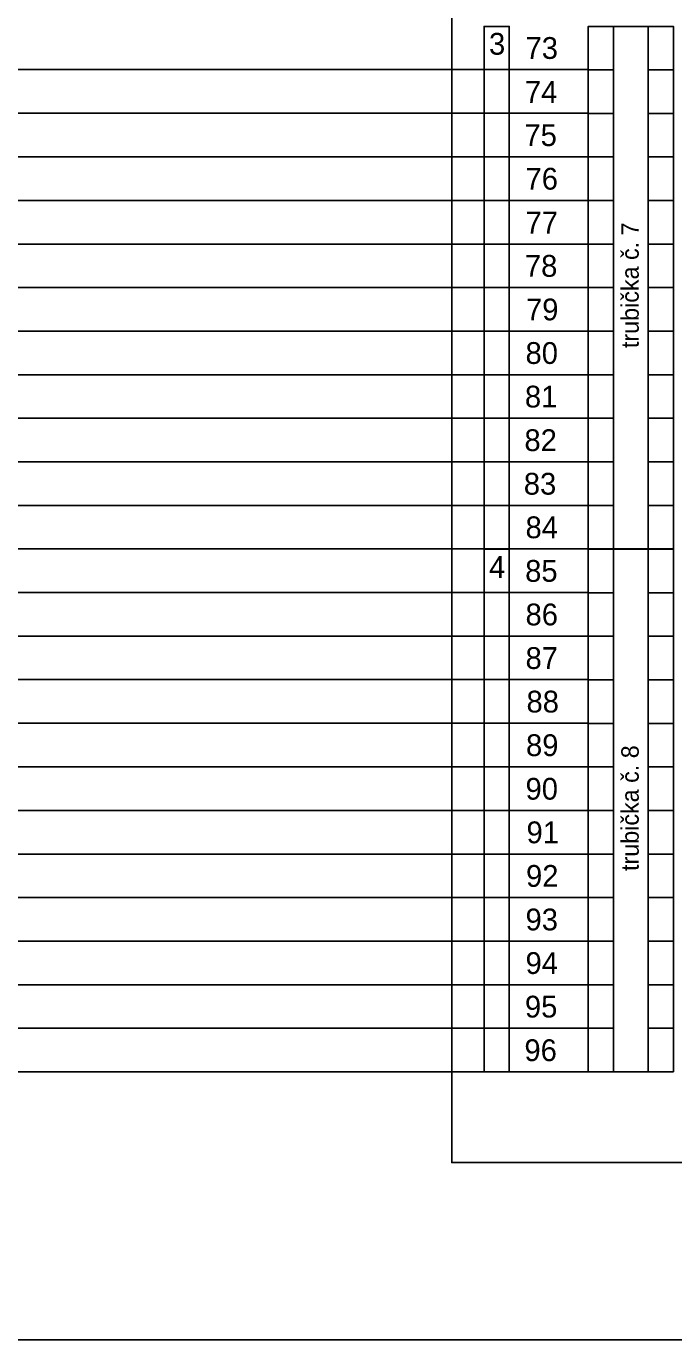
# Model space of a CAD drawing. Extents: x 1901 to 2519, y -3585 to -3154.
# Drawn here: x 1980.5 to 2032.8, y -3585 to -3478.9 of the extents above; entities that cross this region are included whole.
import ezdxf

# ---------------------------------------------------------------- set-up
doc = ezdxf.new("R2010")
doc.units = 0
doc.layers.add('rozvláknění', color=7, linetype='Continuous')
doc.layers.add('Vrstva 4', color=7, linetype='Continuous')

msp = doc.modelspace()

# ---------------------------------------------------------------- linework, layer by layer
at = {"layer": 'rozvláknění'}
for p, q in [((1933.19, -3482.36), (2025.9, -3482.36)), ((1933.19, -3485.88), (2025.9, -3485.88)), ((1933.19, -3489.4), (2025.9, -3489.4)), ((1933.19, -3492.94), (2025.9, -3492.94)), ((1933.19, -3496.46), (2025.9, -3496.46)), ((1933.19, -3499.97), (2025.9, -3499.98)), ((1933.19, -3503.49), (2025.9, -3503.49)), ((1933.19, -3507.01), (2025.9, -3507.01)), ((1933.19, -3510.53), (2025.9, -3510.53)), ((1933.19, -3514.05), (2025.9, -3514.05)), ((1933.19, -3517.56), (2025.9, -3517.57)), ((1933.19, -3521.08), (2025.9, -3521.08)), ((1933.19, -3524.6), (2025.9, -3524.6)), ((1933.19, -3528.12), (2025.9, -3528.12)), ((1933.19, -3531.64), (2025.9, -3531.64)), ((1933.19, -3535.16), (2025.9, -3535.16)), ((1933.19, -3538.67), (2025.9, -3538.68)), ((1933.19, -3542.21), (2025.9, -3542.22)), ((1933.19, -3545.73), (2025.9, -3545.73)), ((1933.19, -3549.25), (2025.9, -3549.25)), ((1933.19, -3552.77), (2025.9, -3552.77)), ((1933.19, -3556.29), (2025.9, -3556.29)), ((1933.19, -3559.8), (2025.9, -3559.81)), ((1933.19, -3563.32), (2025.9, -3563.32))]:
    msp.add_line(p, q, dxfattribs=at)
for points in [[(2014.87, -3178.54), (2059.52, -3178.54), (2059.52, -3570.66), (2014.87, -3570.66)], [(2019.52, -3521.08), (2017.48, -3521.08), (2017.48, -3478.87), (2019.52, -3478.87)], [(2025.9, -3478.87), (2027.94, -3478.87), (2027.94, -3482.38), (2025.9, -3482.38)], [(2025.9, -3478.87), (2027.94, -3478.87), (2027.94, -3482.38), (2025.9, -3482.38)], [(2027.94, -3478.87), (2030.73, -3478.87), (2030.73, -3521.08), (2027.94, -3521.08)], [(2030.73, -3478.87), (2032.77, -3478.87), (2032.77, -3482.38), (2030.73, -3482.38)], [(2030.73, -3478.87), (2032.77, -3478.87), (2032.77, -3482.38), (2030.73, -3482.38)], [(2025.9, -3482.38), (2027.94, -3482.38), (2027.94, -3485.9), (2025.9, -3485.9)], [(2025.9, -3482.38), (2027.94, -3482.38), (2027.94, -3485.9), (2025.9, -3485.9)], [(2030.73, -3482.38), (2032.77, -3482.38), (2032.77, -3485.9), (2030.73, -3485.9)], [(2030.73, -3482.38), (2032.77, -3482.38), (2032.77, -3485.9), (2030.73, -3485.9)], [(2025.9, -3485.9), (2027.94, -3485.9), (2027.94, -3489.42), (2025.9, -3489.42)], [(2025.9, -3485.9), (2027.94, -3485.9), (2027.94, -3489.42), (2025.9, -3489.42)], [(2030.73, -3485.9), (2032.77, -3485.9), (2032.77, -3489.42), (2030.73, -3489.42)], [(2030.73, -3485.9), (2032.77, -3485.9), (2032.77, -3489.42), (2030.73, -3489.42)], [(2025.9, -3489.42), (2027.94, -3489.42), (2027.94, -3492.94), (2025.9, -3492.94)], [(2025.9, -3489.42), (2027.94, -3489.42), (2027.94, -3492.94), (2025.9, -3492.94)], [(2030.73, -3489.42), (2032.77, -3489.42), (2032.77, -3492.94), (2030.73, -3492.94)], [(2030.73, -3489.42), (2032.77, -3489.42), (2032.77, -3492.94), (2030.73, -3492.94)], [(2025.9, -3492.94), (2027.94, -3492.94), (2027.94, -3496.46), (2025.9, -3496.46)], [(2025.9, -3492.94), (2027.94, -3492.94), (2027.94, -3496.46), (2025.9, -3496.46)], [(2030.73, -3492.94), (2032.77, -3492.94), (2032.77, -3496.46), (2030.73, -3496.46)], [(2030.73, -3492.94), (2032.77, -3492.94), (2032.77, -3496.46), (2030.73, -3496.46)], [(2025.9, -3496.46), (2027.94, -3496.46), (2027.94, -3499.98), (2025.9, -3499.98)], [(2025.9, -3496.46), (2027.94, -3496.46), (2027.94, -3499.98), (2025.9, -3499.98)], [(2030.73, -3496.46), (2032.77, -3496.46), (2032.77, -3499.98), (2030.73, -3499.98)], [(2030.73, -3496.46), (2032.77, -3496.46), (2032.77, -3499.98), (2030.73, -3499.98)], [(2025.9, -3499.98), (2027.94, -3499.98), (2027.94, -3503.49), (2025.9, -3503.49)], [(2025.9, -3499.98), (2027.94, -3499.98), (2027.94, -3503.49), (2025.9, -3503.49)], [(2030.73, -3499.98), (2032.77, -3499.98), (2032.77, -3503.49), (2030.73, -3503.49)], [(2030.73, -3499.98), (2032.77, -3499.98), (2032.77, -3503.49), (2030.73, -3503.49)], [(2025.9, -3503.49), (2027.94, -3503.49), (2027.94, -3507.01), (2025.9, -3507.01)], [(2025.9, -3503.49), (2027.94, -3503.49), (2027.94, -3507.01), (2025.9, -3507.01)], [(2030.73, -3503.49), (2032.77, -3503.49), (2032.77, -3507.01), (2030.73, -3507.01)], [(2030.73, -3503.49), (2032.77, -3503.49), (2032.77, -3507.01), (2030.73, -3507.01)], [(2025.9, -3507.01), (2027.94, -3507.01), (2027.94, -3510.53), (2025.9, -3510.53)], [(2025.9, -3507.01), (2027.94, -3507.01), (2027.94, -3510.53), (2025.9, -3510.53)], [(2030.73, -3507.01), (2032.77, -3507.01), (2032.77, -3510.53), (2030.73, -3510.53)], [(2030.73, -3507.01), (2032.77, -3507.01), (2032.77, -3510.53), (2030.73, -3510.53)], [(2025.9, -3510.53), (2027.94, -3510.53), (2027.94, -3514.05), (2025.9, -3514.05)], [(2025.9, -3510.53), (2027.94, -3510.53), (2027.94, -3514.05), (2025.9, -3514.05)], [(2030.73, -3510.53), (2032.77, -3510.53), (2032.77, -3514.05), (2030.73, -3514.05)], [(2030.73, -3510.53), (2032.77, -3510.53), (2032.77, -3514.05), (2030.73, -3514.05)], [(2025.9, -3514.05), (2027.94, -3514.05), (2027.94, -3517.57), (2025.9, -3517.57)], [(2025.9, -3514.05), (2027.94, -3514.05), (2027.94, -3517.57), (2025.9, -3517.57)], [(2030.73, -3514.05), (2032.77, -3514.05), (2032.77, -3517.57), (2030.73, -3517.57)], [(2030.73, -3514.05), (2032.77, -3514.05), (2032.77, -3517.57), (2030.73, -3517.57)], [(2025.9, -3517.57), (2027.94, -3517.57), (2027.94, -3521.08), (2025.9, -3521.08)], [(2025.9, -3517.57), (2027.94, -3517.57), (2027.94, -3521.08), (2025.9, -3521.08)], [(2030.73, -3517.57), (2032.77, -3517.57), (2032.77, -3521.08), (2030.73, -3521.08)], [(2030.73, -3517.57), (2032.77, -3517.57), (2032.77, -3521.08), (2030.73, -3521.08)], [(2019.52, -3563.32), (2017.48, -3563.32), (2017.48, -3521.11), (2019.52, -3521.11)], [(2025.9, -3521.11), (2027.94, -3521.11), (2027.94, -3524.62), (2025.9, -3524.62)], [(2025.9, -3521.11), (2027.94, -3521.11), (2027.94, -3524.62), (2025.9, -3524.62)], [(2027.94, -3521.11), (2030.73, -3521.11), (2030.73, -3563.32), (2027.94, -3563.32)], [(2030.73, -3521.11), (2032.77, -3521.11), (2032.77, -3524.62), (2030.73, -3524.62)], [(2030.73, -3521.11), (2032.77, -3521.11), (2032.77, -3524.62), (2030.73, -3524.62)], [(2025.9, -3524.62), (2027.94, -3524.62), (2027.94, -3528.14), (2025.9, -3528.14)], [(2025.9, -3524.62), (2027.94, -3524.62), (2027.94, -3528.14), (2025.9, -3528.14)], [(2030.73, -3524.62), (2032.77, -3524.62), (2032.77, -3528.14), (2030.73, -3528.14)], [(2030.73, -3524.62), (2032.77, -3524.62), (2032.77, -3528.14), (2030.73, -3528.14)], [(2025.9, -3528.14), (2027.94, -3528.14), (2027.94, -3531.66), (2025.9, -3531.66)], [(2025.9, -3528.14), (2027.94, -3528.14), (2027.94, -3531.66), (2025.9, -3531.66)], [(2030.73, -3528.14), (2032.77, -3528.14), (2032.77, -3531.66), (2030.73, -3531.66)], [(2030.73, -3528.14), (2032.77, -3528.14), (2032.77, -3531.66), (2030.73, -3531.66)], [(2025.9, -3531.66), (2027.94, -3531.66), (2027.94, -3535.18), (2025.9, -3535.18)], [(2025.9, -3531.66), (2027.94, -3531.66), (2027.94, -3535.18), (2025.9, -3535.18)], [(2030.73, -3531.66), (2032.77, -3531.66), (2032.77, -3535.18), (2030.73, -3535.18)], [(2030.73, -3531.66), (2032.77, -3531.66), (2032.77, -3535.18), (2030.73, -3535.18)], [(2025.9, -3535.18), (2027.94, -3535.18), (2027.94, -3538.7), (2025.9, -3538.7)], [(2025.9, -3535.18), (2027.94, -3535.18), (2027.94, -3538.7), (2025.9, -3538.7)], [(2030.73, -3535.18), (2032.77, -3535.18), (2032.77, -3538.7), (2030.73, -3538.7)], [(2030.73, -3535.18), (2032.77, -3535.18), (2032.77, -3538.7), (2030.73, -3538.7)], [(2025.9, -3538.7), (2027.94, -3538.7), (2027.94, -3542.22), (2025.9, -3542.22)], [(2025.9, -3538.7), (2027.94, -3538.7), (2027.94, -3542.22), (2025.9, -3542.22)], [(2030.73, -3538.7), (2032.77, -3538.7), (2032.77, -3542.22), (2030.73, -3542.22)], [(2030.73, -3538.7), (2032.77, -3538.7), (2032.77, -3542.22), (2030.73, -3542.22)], [(2025.9, -3542.22), (2027.94, -3542.22), (2027.94, -3545.73), (2025.9, -3545.73)], [(2025.9, -3542.22), (2027.94, -3542.22), (2027.94, -3545.73), (2025.9, -3545.73)], [(2030.73, -3542.22), (2032.77, -3542.22), (2032.77, -3545.73), (2030.73, -3545.73)], [(2030.73, -3542.22), (2032.77, -3542.22), (2032.77, -3545.73), (2030.73, -3545.73)], [(2025.9, -3545.73), (2027.94, -3545.73), (2027.94, -3549.25), (2025.9, -3549.25)], [(2025.9, -3545.73), (2027.94, -3545.73), (2027.94, -3549.25), (2025.9, -3549.25)], [(2030.73, -3545.73), (2032.77, -3545.73), (2032.77, -3549.25), (2030.73, -3549.25)], [(2030.73, -3545.73), (2032.77, -3545.73), (2032.77, -3549.25), (2030.73, -3549.25)], [(2025.9, -3549.25), (2027.94, -3549.25), (2027.94, -3552.77), (2025.9, -3552.77)], [(2025.9, -3549.25), (2027.94, -3549.25), (2027.94, -3552.77), (2025.9, -3552.77)], [(2030.73, -3549.25), (2032.77, -3549.25), (2032.77, -3552.77), (2030.73, -3552.77)], [(2030.73, -3549.25), (2032.77, -3549.25), (2032.77, -3552.77), (2030.73, -3552.77)], [(2025.9, -3552.77), (2027.94, -3552.77), (2027.94, -3556.29), (2025.9, -3556.29)], [(2025.9, -3552.77), (2027.94, -3552.77), (2027.94, -3556.29), (2025.9, -3556.29)], [(2030.73, -3552.77), (2032.77, -3552.77), (2032.77, -3556.29), (2030.73, -3556.29)], [(2030.73, -3552.77), (2032.77, -3552.77), (2032.77, -3556.29), (2030.73, -3556.29)], [(2025.9, -3556.29), (2027.94, -3556.29), (2027.94, -3559.81), (2025.9, -3559.81)], [(2025.9, -3556.29), (2027.94, -3556.29), (2027.94, -3559.81), (2025.9, -3559.81)], [(2030.73, -3556.29), (2032.77, -3556.29), (2032.77, -3559.81), (2030.73, -3559.81)], [(2030.73, -3556.29), (2032.77, -3556.29), (2032.77, -3559.81), (2030.73, -3559.81)], [(2025.9, -3559.81), (2027.94, -3559.81), (2027.94, -3563.32), (2025.9, -3563.32)], [(2025.9, -3559.81), (2027.94, -3559.81), (2027.94, -3563.32), (2025.9, -3563.32)], [(2030.73, -3559.81), (2032.77, -3559.81), (2032.77, -3563.32), (2030.73, -3563.32)], [(2030.73, -3559.81), (2032.77, -3559.81), (2032.77, -3563.32), (2030.73, -3563.32)]]:
    msp.add_lwpolyline(points, close=True, dxfattribs=at)
for points in [[(2019.52, -3478.87), (2017.48, -3478.87), (2017.48, -3521.08), (2019.52, -3521.08), (2019.52, -3478.87)], [(2025.9, -3482.38), (2027.94, -3482.38), (2027.94, -3478.87), (2025.9, -3478.87), (2025.9, -3482.38)], [(2030.73, -3482.38), (2032.77, -3482.38), (2032.77, -3478.87), (2030.73, -3478.87), (2030.73, -3482.38)], [(2025.9, -3485.9), (2027.94, -3485.9), (2027.94, -3482.38), (2025.9, -3482.38), (2025.9, -3485.9)], [(2030.73, -3485.9), (2032.77, -3485.9), (2032.77, -3482.38), (2030.73, -3482.38), (2030.73, -3485.9)], [(2025.9, -3489.42), (2027.94, -3489.42), (2027.94, -3485.9), (2025.9, -3485.9), (2025.9, -3489.42)], [(2030.73, -3489.42), (2032.77, -3489.42), (2032.77, -3485.9), (2030.73, -3485.9), (2030.73, -3489.42)], [(2025.9, -3492.94), (2027.94, -3492.94), (2027.94, -3489.42), (2025.9, -3489.42), (2025.9, -3492.94)], [(2030.73, -3492.94), (2032.77, -3492.94), (2032.77, -3489.42), (2030.73, -3489.42), (2030.73, -3492.94)], [(2025.9, -3496.46), (2027.94, -3496.46), (2027.94, -3492.94), (2025.9, -3492.94), (2025.9, -3496.46)], [(2030.73, -3496.46), (2032.77, -3496.46), (2032.77, -3492.94), (2030.73, -3492.94), (2030.73, -3496.46)], [(2025.9, -3499.98), (2027.94, -3499.98), (2027.94, -3496.46), (2025.9, -3496.46), (2025.9, -3499.98)], [(2030.73, -3499.98), (2032.77, -3499.98), (2032.77, -3496.46), (2030.73, -3496.46), (2030.73, -3499.98)], [(2025.9, -3503.49), (2027.94, -3503.49), (2027.94, -3499.98), (2025.9, -3499.98), (2025.9, -3503.49)], [(2030.73, -3503.49), (2032.77, -3503.49), (2032.77, -3499.98), (2030.73, -3499.98), (2030.73, -3503.49)], [(2025.9, -3507.01), (2027.94, -3507.01), (2027.94, -3503.49), (2025.9, -3503.49), (2025.9, -3507.01)], [(2030.73, -3507.01), (2032.77, -3507.01), (2032.77, -3503.49), (2030.73, -3503.49), (2030.73, -3507.01)], [(2025.9, -3510.53), (2027.94, -3510.53), (2027.94, -3507.01), (2025.9, -3507.01), (2025.9, -3510.53)], [(2030.73, -3510.53), (2032.77, -3510.53), (2032.77, -3507.01), (2030.73, -3507.01), (2030.73, -3510.53)], [(2025.9, -3514.05), (2027.94, -3514.05), (2027.94, -3510.53), (2025.9, -3510.53), (2025.9, -3514.05)], [(2030.73, -3514.05), (2032.77, -3514.05), (2032.77, -3510.53), (2030.73, -3510.53), (2030.73, -3514.05)], [(2025.9, -3517.57), (2027.94, -3517.57), (2027.94, -3514.05), (2025.9, -3514.05), (2025.9, -3517.57)], [(2030.73, -3517.57), (2032.77, -3517.57), (2032.77, -3514.05), (2030.73, -3514.05), (2030.73, -3517.57)], [(2025.9, -3521.08), (2027.94, -3521.08), (2027.94, -3517.57), (2025.9, -3517.57), (2025.9, -3521.08)], [(2030.73, -3521.08), (2032.77, -3521.08), (2032.77, -3517.57), (2030.73, -3517.57), (2030.73, -3521.08)], [(2019.52, -3521.11), (2017.48, -3521.11), (2017.48, -3563.32), (2019.52, -3563.32), (2019.52, -3521.11)], [(2025.9, -3524.62), (2027.94, -3524.62), (2027.94, -3521.11), (2025.9, -3521.11), (2025.9, -3524.62)], [(2030.73, -3524.62), (2032.77, -3524.62), (2032.77, -3521.11), (2030.73, -3521.11), (2030.73, -3524.62)], [(2025.9, -3528.14), (2027.94, -3528.14), (2027.94, -3524.62), (2025.9, -3524.62), (2025.9, -3528.14)], [(2030.73, -3528.14), (2032.77, -3528.14), (2032.77, -3524.62), (2030.73, -3524.62), (2030.73, -3528.14)], [(2025.9, -3531.66), (2027.94, -3531.66), (2027.94, -3528.14), (2025.9, -3528.14), (2025.9, -3531.66)], [(2030.73, -3531.66), (2032.77, -3531.66), (2032.77, -3528.14), (2030.73, -3528.14), (2030.73, -3531.66)], [(2025.9, -3535.18), (2027.94, -3535.18), (2027.94, -3531.66), (2025.9, -3531.66), (2025.9, -3535.18)], [(2030.73, -3535.18), (2032.77, -3535.18), (2032.77, -3531.66), (2030.73, -3531.66), (2030.73, -3535.18)], [(2025.9, -3538.7), (2027.94, -3538.7), (2027.94, -3535.18), (2025.9, -3535.18), (2025.9, -3538.7)], [(2030.73, -3538.7), (2032.77, -3538.7), (2032.77, -3535.18), (2030.73, -3535.18), (2030.73, -3538.7)], [(2025.9, -3542.22), (2027.94, -3542.22), (2027.94, -3538.7), (2025.9, -3538.7), (2025.9, -3542.22)], [(2030.73, -3542.22), (2032.77, -3542.22), (2032.77, -3538.7), (2030.73, -3538.7), (2030.73, -3542.22)], [(2025.9, -3545.73), (2027.94, -3545.73), (2027.94, -3542.22), (2025.9, -3542.22), (2025.9, -3545.73)], [(2030.73, -3545.73), (2032.77, -3545.73), (2032.77, -3542.22), (2030.73, -3542.22), (2030.73, -3545.73)], [(2025.9, -3549.25), (2027.94, -3549.25), (2027.94, -3545.73), (2025.9, -3545.73), (2025.9, -3549.25)], [(2030.73, -3549.25), (2032.77, -3549.25), (2032.77, -3545.73), (2030.73, -3545.73), (2030.73, -3549.25)], [(2025.9, -3552.77), (2027.94, -3552.77), (2027.94, -3549.25), (2025.9, -3549.25), (2025.9, -3552.77)], [(2030.73, -3552.77), (2032.77, -3552.77), (2032.77, -3549.25), (2030.73, -3549.25), (2030.73, -3552.77)], [(2025.9, -3556.29), (2027.94, -3556.29), (2027.94, -3552.77), (2025.9, -3552.77), (2025.9, -3556.29)], [(2030.73, -3556.29), (2032.77, -3556.29), (2032.77, -3552.77), (2030.73, -3552.77), (2030.73, -3556.29)], [(2025.9, -3559.81), (2027.94, -3559.81), (2027.94, -3556.29), (2025.9, -3556.29), (2025.9, -3559.81)], [(2030.73, -3559.81), (2032.77, -3559.81), (2032.77, -3556.29), (2030.73, -3556.29), (2030.73, -3559.81)], [(2025.9, -3563.32), (2027.94, -3563.32), (2027.94, -3559.81), (2025.9, -3559.81), (2025.9, -3563.32)], [(2030.73, -3563.32), (2032.77, -3563.32), (2032.77, -3559.81), (2030.73, -3559.81), (2030.73, -3563.32)]]:
    msp.add_lwpolyline(points, dxfattribs=at)
at = {"layer": 'Vrstva 4'}
msp.add_lwpolyline([(1901.22, -3154.47), (2516.22, -3154.47), (2516.22, -3584.97), (1901.22, -3584.97)], close=True, dxfattribs=at)

# ---------------------------------------------------------------- texts
at = {"layer": 'rozvláknění'}
for s, p in [('3', (2017.88, -3481.16)), ('73', (2020.83, -3481.5)), ('74', (2020.78, -3485.05)), ('75', (2020.74, -3488.54)), ('76', (2020.83, -3492.06)), ('77', (2020.83, -3495.61)), ('78', (2020.78, -3499.1)), ('79', (2020.87, -3502.62)), ('80', (2020.83, -3506.14)), ('81', (2020.78, -3509.66)), ('82', (2020.74, -3513.18)), ('83', (2020.69, -3516.7)), ('84', (2020.83, -3520.22)), ('4', (2017.88, -3523.43)), ('85', (2020.8, -3523.74)), ('86', (2020.83, -3527.26)), ('87', (2020.83, -3530.78)), ('88', (2020.91, -3534.3)), ('89', (2020.87, -3537.82)), ('90', (2020.83, -3541.34)), ('91', (2020.91, -3544.86)), ('92', (2020.87, -3548.38)), ('93', (2020.83, -3551.9)), ('94', (2020.83, -3555.42)), ('95', (2020.78, -3558.94)), ('96', (2020.74, -3562.46))]:
    msp.add_text(s, height=1.76, dxfattribs=at).set_placement(p)
for s, p in [('trubička č. 7', (2029.97, -3504.86)), ('trubička č. 8', (2029.97, -3547.1))]:
    msp.add_text(s, height=1.408, rotation=90, dxfattribs=at).set_placement(p)

doc.saveas('drawing.dxf')
